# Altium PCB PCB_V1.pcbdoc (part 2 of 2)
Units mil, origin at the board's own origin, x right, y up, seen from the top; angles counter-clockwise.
Board outline 2047.24 x 3937.01 mil, 2 copper layers (Top Layer, Bottom Layer), stack 62.206 mil thick; 59 components, 45 nets, 231 pads, 209 vias.
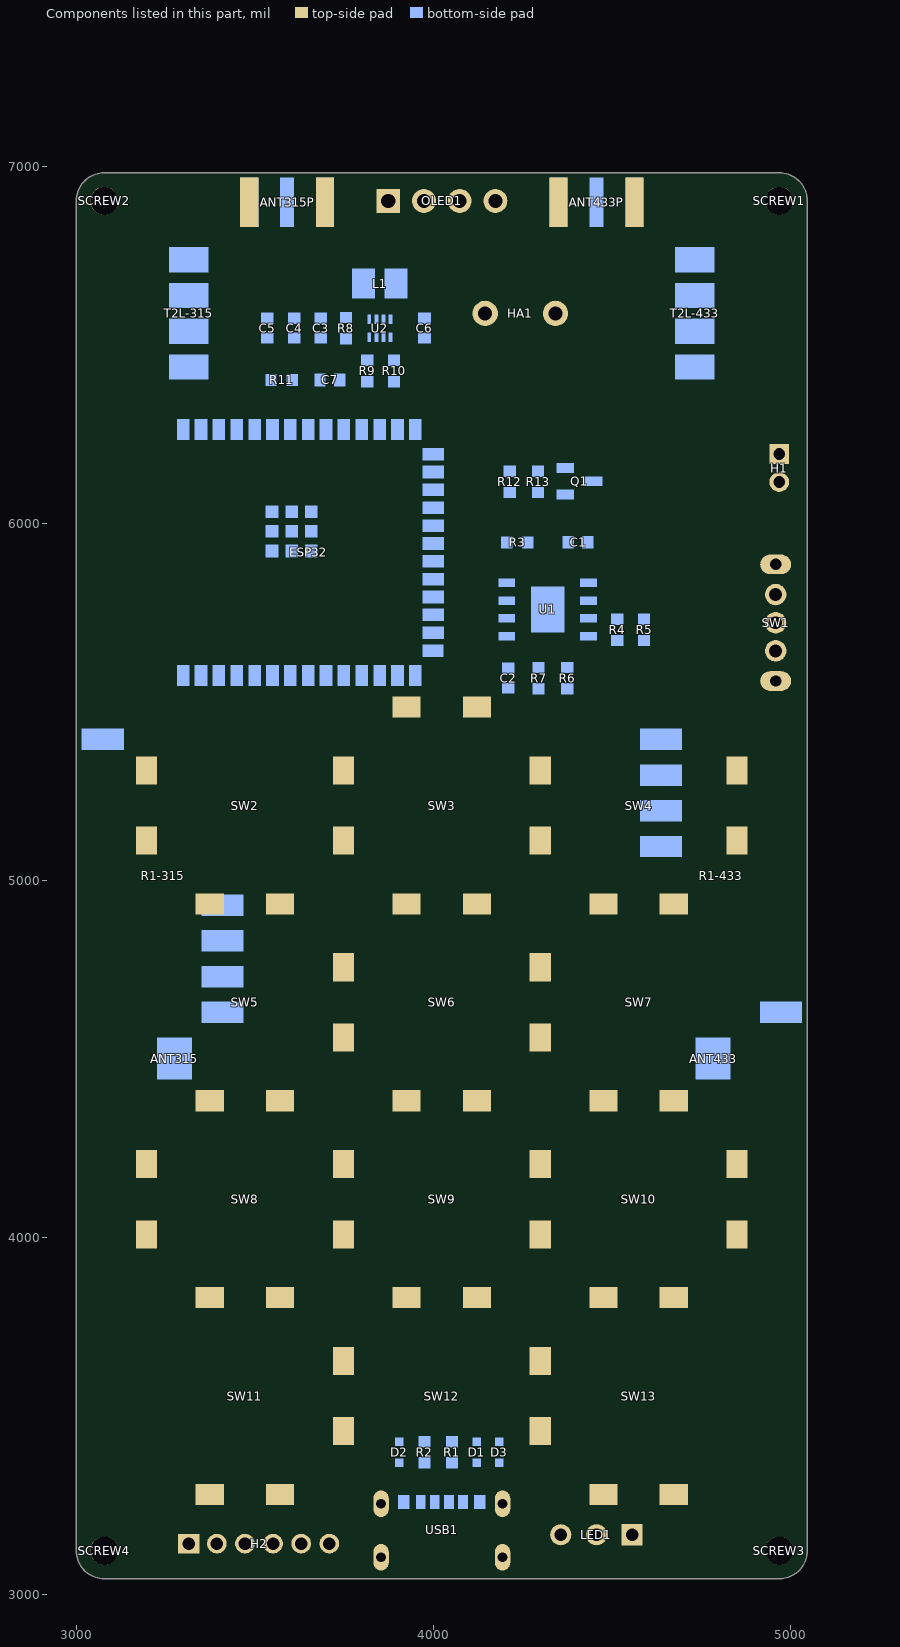
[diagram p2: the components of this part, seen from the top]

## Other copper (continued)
Bottom Layer:
  region net GND: 3530,6051.2 3675,6051.2 3675,5901.2 3530,5901.2
  region net $1N28916: 3907.72,6438.15 3871.33,6438.15 3871.46,6474.41 3854.1,6507.94 3854.1,6534.47 3885.01,6534.47 3885.16,6506.36 3907.72,6473.25
  region net $1N28920: 3833,6437.81 3797.28,6437.81 3797.28,6473.25 3760.6,6473.25 3735,6498.85 3735,6534.71 3826.2,6534.71 3826.2,6507 3833,6500.2
  region net EN: 3590.55,6416.94 3699.21,6416.94 3699.21,6383.48 3590.55,6383.48
  region net $1N28917: 3865.5,6557.67 3854.4,6557.67 3854.4,6585.15 3862.46,6628.72 3862.46,6716.2 3929.3,6716.2 3929.3,6626.2 3905.12,6626.2 3865.5,6587.16
  region net VCC: 3872.6,6557.82 3872.6,6585.62 3885.6,6585.6 3956.21,6590.6 3995,6590.6 3995,6557.82
  region net $1N28918: 3845.8,6557.89 3834.78,6557.89 3834.63,6584.73 3793.07,6626.56 3771.69,6626.52 3771.69,6716.14 3836.82,6716.14 3836.31,6715.63 3836.31,6628.63 3845.79,6584.73
  region net +3.3V: 3825.72,6584.7 3825.72,6556.75 3515.64,6556.75 3515.64,6591.31 3516.34,6592.01 3771.88,6592.01 3779.19,6584.7
  region net GND: 3994.86,6550.77 3994.79,6502.17 3994.68,6502.06 3955.99,6502.06 3955.56,6502.5 3955.56,6540.33 3954.93,6540.95 3851.52,6540.95 3845.82,6535.26 3845.82,6507.49 3834.35,6507.49 3834.35,6535.11 3828.54,6540.92 3710.47,6540.92 3703.19,6533.64 3703.19,6500.95 3516.92,6500.95 3516.28,6501.59 3516.28,6550.78
  region net GND: 3720.59,6419.62 3833.08,6419.62 3833.08,6380.39 3720.59,6380.39
  region net VBUS: 4095.18,3223.89 4070.18,3223.89 ccw(c3973.62,3223.89) 4068.9,3239.57 4096.46,3239.57 ccw(c4191.84,3223.89)
  region net VBUS: 4070.18,3293.88 4095.18,3293.88 ccw(c4183.03,3293.88) 4096.46,3278.94 4068.9,3278.94 ccw(c3982.32,3293.88)
  region net $1N28864: 4030.81,3316.44 4055.81,3316.44 ccw(c4605.98,3316.44) 4057.09,3278.94 4029.53,3278.94 ccw(c3480.63,3316.44)
  region net $1N28863: 3991.44,3316.44 4016.44,3316.44 ccw(c4566.61,3316.44) 4017.72,3278.94 3990.16,3278.94 ccw(c3441.26,3316.44)
  region net VBUS: 3977.07,3226.63 3952.07,3226.63 ccw(c3886.05,3226.63) 3950.79,3239.57 3978.35,3239.57 ccw(c4043.08,3226.63)
  region net TXD: 3599.85,3165.61 3606.93,3172.68 3608.05,3171.76 3609.35,3171.02 3610.81,3170.45 3612.39,3170.02 3615.84,3169.56 3619.47,3169.47 3623.08,3169.63 3626.46,3169.89 3629.38,3170.1 3631.65,3170.12 3602.42,3140.89 3602.44,3143.15 3602.65,3146.08 3602.91,3149.45 3603.06,3153.07 3602.98,3156.7 3602.51,3160.14 3602.09,3161.73 3601.52,3163.19 3600.78,3164.49
  region net EN: 3464.41,3177.75 3474.41,3182.3 3474.55,3180.85 3474.97,3179.4 3475.62,3177.95 3476.47,3176.51 3478.66,3173.71 3481.28,3171.04 3484.08,3168.58 3486.8,3166.38 3490.98,3163.01 3449.89,3158.46 3451.31,3160.11 3453.33,3162.06 3458.19,3166.69 3460.55,3169.3 3462.53,3172.04 3463.31,3173.44 3463.9,3174.87 3464.28,3176.31
  region net BOOT: 3423.77,3119.62 3416.69,3112.55 3415.57,3113.47 3414.27,3114.21 3412.81,3114.79 3411.23,3115.21 3407.78,3115.68 3404.15,3115.76 3400.54,3115.6 3397.16,3115.35 3394.24,3115.14 3391.97,3115.11 3421.21,3144.34 3421.18,3142.08 3420.97,3139.15 3420.71,3135.78 3420.56,3132.17 3420.64,3128.53 3421.11,3125.09 3421.53,3123.5 3422.1,3122.05 3422.84,3120.74
  region net CHG_P: 4176.53,5742.6 4182.67,5750.59 ccw(c4198.58,5771.81) 4198.58,5745.29 4181.83,5726.69 ccw(c4155.32,5726.69)
  region net CHG_P: 4181.27,5716.37 4176.53,5725.77 ccw(c4155.32,5741.68) 4181.83,5741.68 4197.18,5721.67 ccw(c4197.18,5695.15)
  region net B+: 4419.45,5890.29 4449.45,5890.29 ccw(c4571.18,5890.29) 4458.08,5845.29 4410.83,5845.29 ccw(c4297.69,5890.29)
  region net $1N7064: 4488.08,5793.48 4488.08,5773.48 ccw(c4488.08,5524.09) 4458.08,5771.67 4458.08,5795.29 ccw(c4488.08,6042.87)
  region net $1N6847: 4488.08,5739.68 4488.08,5719.68 ccw(c4458.08,5494.62) 4458.08,5721.67 4458.08,5745.29 ccw(c4488.08,5822.66)
  region net VBUS: 4446.95,5634.17 4421.95,5634.17 ccw(c4353.17,5634.17) 4410.83,5671.67 4458.08,5671.67 ccw(c4515.74,5634.17)
  region net VBUS: 4407.28,5673.48 4407.28,5693.48 ccw(c4407.28,5697.87) 4410.83,5695.29 4410.83,5671.67 ccw(c4407.28,5669.09)
  region net +3.3V: 3954.34,6859.33 3931.15,6878.56 3932.34,6879.87 3933.44,6881.29 3935.35,6884.4 3936.9,6887.75 3938.13,6891.18 3939.04,6894.54 3939.67,6897.68 3940.03,6900.44 3940.16,6902.69 3977.57,6869.22 3972.76,6868.36 3969.76,6867.58 3966.56,6866.54 3963.28,6865.21 3960.06,6863.58 3957.04,6861.63
  region net +3.3V: 4016.09,6878.56 3992.9,6859.33 3990.21,6861.63 3987.18,6863.58 3983.96,6865.21 3980.68,6866.54 3977.48,6867.58 3974.48,6868.36 3969.67,6869.22 4007.08,6902.69 4007.21,6900.44 4007.58,6897.68 4008.2,6894.54 4009.12,6891.18 4010.34,6887.75 4011.89,6884.4 4013.8,6881.29 4014.9,6879.87
  region net $1N7056: 4546.69,3227.14 4566.69,3227.14 ccw(c4604.19,3227.14) 4581.69,3197.14 4531.69,3197.14 ccw(c4509.19,3227.14)
  region net VBUS: 4437.11,3130.35 4419.43,3148.03 4421.43,3150.44 4423.07,3153.2 4424.39,3156.18 4425.41,3159.23 4426.17,3162.22 4426.71,3165.02 4427.22,3169.47 4458.54,3138.15 4454.09,3137.63 4451.3,3137.1 4448.31,3136.33 4445.26,3135.31 4442.28,3134 4439.52,3132.35
  region net $1N11631: 4378.05,3203.11 4392.19,3188.97 4391.16,3187.8 4390.26,3186.49 4388.82,3183.55 4387.79,3180.32 4387.1,3176.97 4386.66,3173.67 4386.41,3170.59 4386.16,3165.77 4354.84,3197.09 4359.67,3197.33 4362.75,3197.58 4366.05,3198.02 4369.4,3198.72 4372.63,3199.75 4375.57,3201.19 4376.88,3202.08
  region net 433_TX: 4832.4,6749.61 4832.4,6719.61 ccw(c4832.4,6653.12) 4787.4,6702.06 4787.4,6772.11 ccw(c4832.4,6805.86)
  region net +3.3V: 4635.52,6617.46 4635.52,6647.46 ccw(c4635.52,6697.25) 4677.17,6669.96 4677.17,6602.06 ccw(c4635.52,6553.42)
  region net GND: 4832.4,6551.2 4832.4,6521.2 ccw(c4832.4,6458.72) 4787.4,6502.06 4787.4,6572.93 ccw(c4832.4,6608.66)
  region net 433ANT: 4602.17,6412.49 4602.17,6462.49 ccw(c4602.17,6737.29) 4677.17,6472.93 4677.17,6402.06 ccw(c4602.17,6137.7)
  region net 433ANT: 4757.29,6327.06 4707.29,6327.06 ccw(c4598.84,6327.06) 4677.17,6402.06 4787.4,6402.06 ccw(c4865.73,6327.06)
  region net $1N15750: 4440,6176.36 4470,6176.36 ccw(c4818.76,6176.36) 4472.92,6131.36 4423.7,6131.36 ccw(c4369.73,6176.36)
  region net $1N6847: 4467.99,5719.68 4467.99,5739.68 ccw(c4467.99,5806.99) 4497.99,5746.73 4497.99,5714.98 ccw(c4467.99,5621.5)
  region net $1N11631: 4525,5625.66 4505,5625.66 ccw(c4437.28,5625.66) 4497.99,5655.66 4532.01,5655.66 ccw(c4592.72,5625.66)
  region net $1N7064: 4580,5756.2 4600,5756.2 ccw(c4609.9,5756.2) 4607.01,5746.73 4572.99,5746.73 ccw(c4570.1,5756.2)
  region net $1N7056: 4600,5625.66 4580,5625.66 ccw(c4512.28,5625.66) 4572.99,5655.66 4607.01,5655.66 ccw(c4667.72,5625.66)
  region net CHG_P: 4190.1,5923.89 4184.16,5932.09 ccw(c4162.95,5948) 4189.46,5948 4206.01,5929.19 ccw(c4206.01,5902.67)
  region net 433ANT: 4873.23,4525.88 4873.23,4475.88 ccw(c4873.23,4434.71) 4832.68,4441.83 4832.68,4559.94 ccw(c4873.23,4567.05)
  region net 315ANT: 3174.02,4475.88 3174.02,4525.88 ccw(c3174.02,4582.26) 3225.79,4559.94 3225.79,4441.83 ccw(c3174.02,4419.5)
  region net +3.3V: 4357.01,6539.29 4327.01,6539.29 4326.92,6541.16 4326.66,6543.03 4325.71,6546.77 4324.3,6550.41 4322.58,6553.87 4320.69,6557.05 4318.77,6559.88 4315.43,6564.09 4368.58,6564.09 4365.25,6559.88 4363.33,6557.05 4361.44,6553.87 4359.72,6550.41 4358.31,6546.77 4357.36,6543.03 4357.1,6541.16
  region net +3.3V: 4297.29,6611.03 4318.5,6632.24 4319.89,6630.99 4321.4,6629.84 4324.71,6627.87 4328.28,6626.29 4331.95,6625.07 4335.54,6624.15 4338.89,6623.51 4344.23,6622.89 4306.64,6585.31 4306.02,6590.65 4305.38,6594 4304.47,6597.59 4303.24,6601.25 4301.66,6604.82 4299.69,6608.14 4298.55,6609.65
  region net $1N15750: 4189.68,6562.73 4167.35,6542.63 4165.97,6543.89 4164.47,6545.04 4161.18,6547.02 4157.64,6548.62 4154.02,6549.88 4150.48,6550.83 4147.17,6551.52 4141.89,6552.25 4180.57,6588.7 4180.73,6586.29 4181.09,6583.31 4181.68,6579.91 4182.56,6576.28 4183.76,6572.58 4185.32,6568.97 4187.28,6565.63 4188.43,6564.12
  region net GND: 4953.5,6266.36 4983.5,6266.36 ccw(c5070.4,6266.36) 4996.06,6221.36 4940.94,6221.36 ccw(c4866.6,6266.36)
  region net B+: 4449.45,5883.48 4419.45,5883.48 ccw(c4034.87,5883.48) 4416.81,5928.48 4448.31,5928.48 ccw(c5332.55,5928.48)
  region net ADC: 4180.26,5553.29 4196.37,5565.46 ccw(c4227.72,5604.29) 4227.72,5554.39 4192.28,5522.89 ccw(c4147.85,5522.89)
  region net ADC: 4257.72,5548.64 4257.72,5528.64 ccw(c4257.72,5447.48) 4227.72,5522.89 4227.72,5554.39 ccw(c4257.72,5629.8)
  region net VCC: 4360,5635.71 4390,5635.71 ccw(c4534.16,5635.71) 4392.01,5611.73 4357.99,5611.73 ccw(c4215.84,5635.71)
  region net ADC: 4327.99,5528.64 4327.99,5548.64 ccw(c4327.99,5669.72) 4357.99,5552.41 4357.99,5520.66 ccw(c4327.99,5468.23)
  region net ADC: 4247.47,5528.64 4247.47,5548.64 ccw(c4247.47,5669.72) 4277.47,5552.41 4277.47,5520.66 ccw(c4247.47,5468.23)
  region net ADC: 4341.48,5548.64 4341.48,5528.64 ccw(c4341.48,5468.23) 4311.48,5520.66 4311.48,5552.41 ccw(c4341.48,5669.72)
  region net $1N15783: 4276.03,6101.03 4276.03,6071.03 ccw(c4276.03,4914.13) 4231.03,6070.15 4231.03,6101.9 ccw(c4276.03,7257.93)
  region net BUZZER: 4152.02,6130.35 4152.02,6160.35 ccw(c4152.02,7317.25) 4197.02,6161.22 4197.02,6129.47 ccw(c4152.02,4973.45)
  region net $1N15783: 4355.32,6095.18 4355.32,6065.18 ccw(c4310.32,5864.1) 4310.32,6070.15 4310.32,6101.9 ccw(c4355.32,6249.1)
  region net $1N15783: 4231.3,6071.03 4231.3,6101.03 ccw(c4231.3,7257.93) 4276.3,6101.9 4276.3,6070.15 ccw(c4231.3,4914.13)
  region net EN: 3599.17,6376.3 3580.25,6371.52 ccw(c3552.01,6399.75) 3588.78,6384.19 3612.49,6384.19 ccw(c3621.25,6354.22)
  region net +3.3V: 3507,6386.2 3507,6416.2 ccw(c3507,6542.86) 3529.46,6418.21 3529.46,6384.19 ccw(c3507,6259.53)
  region net 315ANT: 3099.02,5289.82 3049.02,5289.82 ccw(c2949.4,5289.82) 3014.96,5364.82 3133.07,5364.82 ccw(c3198.63,5289.82)
  region net 315ANT: 3049.02,5499.82 3099.02,5499.82 ccw(c3198.63,5499.82) 3133.07,5424.82 3014.96,5424.82 ccw(c2949.4,5499.82)
  region net 315_RX: 3379.69,4830.57 3439.69,4830.57 ccw(c3538.54,4830.57) 3468.74,4760.57 3350.63,4760.57 ccw(c3280.84,4830.57)
  region net 315_RX: 3439.69,4730.57 3379.69,4730.57 ccw(c3280.84,4730.57) 3350.63,4800.57 3468.74,4800.57 ccw(c3538.54,4730.57)
  region net 315_RX: 3491.37,4845.57 3491.37,4815.57 ccw(c3491.37,4791) 3468.74,4800.57 3468.74,4860.57 ccw(c3491.37,4870.14)
  region net +3.3V: 3394.41,5005.57 3424.41,5005.57 ccw(c3480.66,5005.57) 3446.91,4960.57 3371.91,4960.57 ccw(c3338.16,5005.57)
  region net 433ANT: 4972.99,4525.57 4873.23,4525.88 ccw(c4873.23,4574.45) 4914.17,4600.57 5032.28,4600.57 ccw(c6683.1,3234.58)
  region net 433ANT: 4948.23,4735.57 4998.23,4735.57 ccw(c5097.84,4735.57) 5032.28,4660.57 4914.17,4660.57 ccw(c4848.61,4735.57)
  region net 433_RX: 4667.56,5194.82 4607.56,5194.82 ccw(c4508.71,5194.82) 4578.5,5264.82 4696.61,5264.82 ccw(c4766.41,5194.82)
  region net 433_RX: 4607.56,5294.82 4667.56,5294.82 ccw(c4766.41,5294.82) 4696.61,5224.82 4578.5,5224.82 ccw(c4508.71,5294.82)
  region net 433_RX: 4717.52,5261.49 4736.84,5233.85 ccw(c17512.76,-2753.85) 4696.61,5169.15 4647.88,5224.82 ccw(c4647.88,5309.28)
  region net +3.3V: 4713.62,5109.82 4713.62,5079.82 ccw(c4713.62,5062.68) 4696.61,5064.82 4696.61,5124.82 ccw(c4713.62,5126.96)
  region net 315_TX: 3415.27,6429.5 3407.97,6396.58 ccw(c3385.28,6373.47) 3370.08,6402.07 3370.08,6471.05 ccw(c3560.59,6632.9)
  region net +3.3V: 3415.08,6552.5 3415.08,6522.5 ccw(c3415.08,6462.73) 3370.08,6502.07 3370.08,6572.93 ccw(c3415.08,6612.27)
  region net 315ANT: 3184.84,6712.5 3184.84,6762.5 ccw(c3184.84,7037.3) 3259.84,6772.93 3259.84,6702.07 ccw(c3184.84,6437.71)
  region net 315ANT: 3445.08,6762.5 3445.08,6712.5 ccw(c3445.08,6437.71) 3370.08,6702.07 3370.08,6772.93 ccw(c3445.08,7037.3)
  region net $1N28863: 3946.81,3378.86 3946.81,3358.86 ccw(c3946.81,3089.53) 3916.81,3357.19 3916.81,3380.81 ccw(c3946.81,3611.08)
  region net $1N28864: 4106.27,3381.36 4106.27,3356.36 ccw(c4106.27,3146.37) 4068.77,3352.99 4068.77,3384.74 ccw(c4106.27,3591.35)
  region net $1N28864: 4055.81,3315.49 4030.81,3315.49 ccw(c3854.73,3352.99) 4034.76,3352.99 4068.77,3352.99 ccw(c4116.52,3315.49)
  region net $1N28863: 3927.99,3358.86 3927.99,3378.86 ccw(c3927.99,3458.39) 3957.99,3384.74 3957.99,3352.99 ccw(c3927.99,3279.33)
  region net $1N28863: 4010.92,3350.62 3992.11,3334.07 ccw(c3942.07,3284.03) 3957.99,3352.99 3992.01,3384.74 ccw(c4060.96,3400.66)
  region net +3.3V: 3670,6634.51 3700,6634.51 ccw(c4074.08,6634.51) 3702.72,6589.51 3667.28,6589.51 ccw(c3295.92,6634.51)
  region net +3.3V: 3472.28,6559.2 3472.28,6589.2 ccw(c3472.28,9876.7) 3517.28,6589.51 3517.28,6558.01 ccw(c3472.28,5706.33)
  region net VCC: 4037.72,6588.76 4037.72,6558.76 ccw(c4037.72,5204.78) 3992.72,6558.01 3992.72,6589.51 ccw(c4037.72,7942.74)
  region net VCC: 3952.01,6410.94 3952.01,6380.94 ccw(c3952.01,2747.89) 3907.01,6380.66 3907.01,6412.41 ccw(c3952.01,7099.39)
  region net +3.3V: 3364.41,6188.17 3334.41,6188.17 ccw(c2959.97,6188.17) 3331.69,6233.17 3367.13,6233.17 ccw(c3738.14,6188.17)
  region net EN: 3387,6307.22 3397,6307.22 ccw(c3415.75,6307.22) 3404.5,6292.22 3381.69,6292.22 ccw(c3363.14,6307.22)
  region net EN: 3404.41,6218.17 3394.41,6218.17 ccw(c3375.66,6218.17) 3386.91,6233.17 3411.91,6233.17 ccw(c3423.16,6218.17)
  region net 315_TX: 3433.42,6335.93 3463.42,6335.93 ccw(c3722.86,6335.93) 3467.13,6292.22 3431.69,6292.22 ccw(c2879.13,6335.93)
  region net 315_RX: 3514.41,6202.61 3484.41,6202.61 ccw(c3311.17,6202.61) 3481.69,6233.17 3517.13,6233.17 ccw(c3687.66,6202.61)
  region net KEY_BACK: 3554.41,6228.17 3544.41,6228.17 ccw(c3536.91,6225.04) 3536.91,6233.17 3561.91,6233.17 ccw(c3561.91,6225.04)
  region net KEY_8: 3604.41,6218.17 3594.41,6218.17 ccw(c3575.66,6218.17) 3586.91,6233.17 3611.91,6233.17 ccw(c3623.16,6218.17)
  region net KEY_7: 3654.41,6228.17 3644.41,6228.17 ccw(c3636.91,6225.04) 3636.91,6233.17 3661.91,6233.17 ccw(c3661.91,6225.04)
  region net KEY_6: 3704.41,6228.17 3694.41,6228.17 ccw(c3686.91,6225.04) 3686.91,6233.17 3711.91,6233.17 ccw(c3711.91,6225.04)
  region net KEY_5: 3754.41,6218.17 3744.41,6218.17 ccw(c3725.66,6218.17) 3736.91,6233.17 3761.91,6233.17 ccw(c3773.16,6218.17)
  region net KEY_4: 3804.41,6218.17 3794.41,6218.17 ccw(c3775.66,6218.17) 3786.91,6233.17 3811.91,6233.17 ccw(c3823.16,6218.17)
  region net KEY_3: 3854.41,6218.17 3844.41,6218.17 ccw(c3825.66,6218.17) 3836.91,6233.17 3861.91,6233.17 ccw(c3873.16,6218.17)
  region net KEY_2: 3904.41,6218.17 3894.41,6218.17 ccw(c3875.66,6218.17) 3886.91,6233.17 3911.91,6233.17 ccw(c3923.16,6218.17)
  region net KEY_1: 3954.41,6218.17 3944.41,6218.17 ccw(c3925.66,6218.17) 3936.91,6233.17 3961.91,6233.17 ccw(c3973.16,6218.17)
  region net I2C_SDA: 3994.8,6225.92 4004.8,6225.92 ccw(c4023.55,6225.92) 4012.3,6210.92 3987.3,6210.92 ccw(c3976.05,6225.92)
  region net BUZZER: 4074.33,6107.2 4074.33,6077.2 ccw(c4074.33,5483.75) 4029.33,6075.49 4029.33,6110.92 ccw(c4074.33,6380.92)
  region net KEY_ENTER: 3960.27,6038.21 3960.27,6048.21 ccw(c3960.27,6058.62) 3970.27,6055.71 3970.27,6030.71 ccw(c3960.27,6027.79)
  region net KEY_MENU: 3968.06,5970.19 3964.97,5981.24 ccw(c3943.76,5997.15) 3970.27,5997.15 3983.97,5975.49 ccw(c3983.97,5948.97)
  region net 433_RX: 4074.33,5958.21 4074.33,5928.21 ccw(c4074.33,5554.12) 4029.33,5925.49 4029.33,5960.92 ccw(c4074.33,6332.29)
  region net 433_TX: 4074.33,5908.2 4074.33,5878.2 ccw(c4074.33,5503.88) 4029.33,5875.49 4029.33,5910.92 ccw(c4074.33,6282.04)
  region net ADC: 4034.33,5853.2 4034.33,5833.2 ccw(c4037.78,5825.49) 4029.33,5825.49 4029.33,5860.92 ccw(c4037.79,5860.92)
  region net KEY_9: 3960.27,5788.21 3960.27,5798.21 ccw(c3960.27,5808.62) 3970.27,5805.71 3970.27,5780.71 ccw(c3960.27,5777.79)
  region net BOOT: 3954.41,5529.19 3944.41,5529.19 ccw(c3925.66,5529.19) 3936.91,5544.19 3961.91,5544.19 ccw(c3973.16,5529.19)
  region net RXD: 3504.41,5529.19 3494.41,5529.19 ccw(c3475.66,5529.19) 3486.91,5544.19 3511.91,5544.19 ccw(c3523.16,5529.19)
  region net TXD: 3455,5529.19 3445,5529.19 ccw(c3426.25,5529.19) 3437.5,5544.19 3462.5,5544.19 ccw(c3473.75,5529.19)
  region net I2C_SCL: 3403.83,5611.14 3423.4,5616.57 ccw(c3445.48,5594.49) 3415.51,5603.24 3390.51,5603.24 ccw(c3381.75,5633.22)
  region net CHG_P: 3344.41,5613.24 3354.41,5613.24 ccw(c3364.83,5613.24) 3361.91,5603.24 3336.91,5603.24 ccw(c3333.99,5613.24)
  region net GND: 3314.41,5520.35 3284.41,5520.35 ccw(c3178.48,5520.35) 3281.69,5544.19 3317.13,5544.19 ccw(c3420.34,5520.35)
  region net RXD: 3494.41,5329.85 3504.41,5327.02 3504.69,5325.38 3505.43,5323.17 3506.47,5320.78 3507.66,5318.61 3489.88,5321.45 3491.54,5323.22 3492.99,5325.48 3494.02,5327.82 3494.31,5328.9
  region net KEY_BACK: 3545.87,6224.63 3552.94,6231.7 3553.89,6231.24 3555.64,6230.78 3557.84,6230.39 3560.16,6230.15 3547.42,6217.42 3547.18,6219.74 3546.8,6221.94 3546.34,6223.68
  region net KEY_ENTER: 4090.71,5563.54 4085.14,5554.97 4084.42,5555.55 4083.48,5556.1 4081.13,5557.03 4078.52,5557.64 4076.07,5557.79 4087.22,5571.93 4087.83,5569.53 4088.72,5567.06 4089.74,5564.94
  region net KEY_ENTER: 4264.31,5375.8 4271.38,5382.87 4272.91,5381.84 4275.15,5380.88 4277.7,5380.13 4280.16,5379.76 4267.42,5367.02 4267.05,5369.48 4266.31,5372.03 4265.35,5374.28
  region net KEY_1: 3785.88,5724.63 3792.95,5731.71 3793.9,5731.24 3795.64,5730.78 3797.84,5730.39 3800.16,5730.15 3787.43,5717.42 3787.19,5719.74 3786.8,5721.94 3786.34,5723.68
  region net KEY_1: 3681.39,5113.08 3674.32,5120.15 3675.35,5121.67 3676.31,5123.91 3677.05,5126.47 3677.43,5128.92 3690.16,5116.19 3687.71,5115.81 3685.15,5115.07 3682.91,5114.11
  region net KEY_1: 3647.44,5093.27 3654.51,5086.2 3653.47,5084.67 3652.51,5082.43 3651.77,5079.87 3651.4,5077.42 3638.66,5090.16 3641.11,5090.53 3643.67,5091.27 3645.91,5092.23
  region net KEY_2: 3787.44,6053.26 3794.51,6046.19 3793.47,6044.67 3792.51,6042.43 3791.77,6039.87 3791.4,6037.42 3778.66,6050.15 3781.11,6050.53 3783.67,6051.27 3785.91,6052.23
  region net KEY_2: 4097.14,4761.79 4097.14,4751.79 4095.33,4751.45 4093.07,4750.54 4090.74,4749.25 4088.74,4747.78 4088.74,4765.8 4090.74,4764.32 4093.07,4763.04 4095.33,4762.13
  region net KEY_2: 4144.45,4751.79 4144.45,4761.79 4146.25,4762.13 4148.52,4763.04 4150.85,4764.32 4152.85,4765.8 4152.85,4747.78 4150.85,4749.25 4148.52,4750.54 4146.25,4751.45
  region net KEY_3: 3844.41,6234.52 3854.41,6234.52 3854.76,6232.71 3855.66,6230.44 3856.95,6228.11 3858.42,6226.11 3840.41,6226.11 3841.88,6228.11 3843.16,6230.44 3844.07,6232.71
  region net KEY_4: 3782.93,5694.81 3790.01,5701.88 3791.53,5700.85 3793.77,5699.89 3796.33,5699.15 3798.78,5698.77 3786.05,5686.04 3785.67,5688.49 3784.93,5691.05 3783.97,5693.29
  region net KEY_4: 3753.03,5000.44 3743.03,5000.44 3742.69,5002.25 3741.78,5004.52 3740.49,5006.85 3739.02,5008.85 3757.04,5008.85 3755.57,5006.85 3754.28,5004.52 3753.37,5002.25
  region net KEY_4: 3731.68,4691.79 3731.68,4701.79 3733.49,4702.13 3735.76,4703.04 3738.09,4704.32 3740.09,4705.8 3740.09,4687.78 3738.09,4689.25 3735.76,4690.54 3733.49,4691.45
  region net KEY_4: 3743.03,4713.14 3753.03,4713.14 3753.37,4711.33 3754.28,4709.06 3755.57,4706.73 3757.04,4704.73 3739.02,4704.73 3740.49,4706.73 3741.78,4709.06 3742.69,4711.33
  region net KEY_4: 3466.05,4521.89 3473.13,4514.81 3472.09,4513.29 3471.13,4511.05 3470.39,4508.49 3470.01,4506.04 3457.28,4518.77 3459.73,4519.15 3462.29,4519.89 3464.53,4520.85
  region net KEY_5: 3727.44,6133.26 3734.51,6126.19 3733.47,6124.67 3732.51,6122.43 3731.77,6119.87 3731.4,6117.42 3718.66,6130.15 3721.11,6130.53 3723.67,6131.27 3725.91,6132.23
  region net KEY_6: 3695.87,6224.63 3702.94,6231.7 3703.89,6231.24 3705.64,6230.78 3707.84,6230.39 3710.16,6230.15 3697.42,6217.42 3697.18,6219.74 3696.8,6221.94 3696.34,6223.68
  region net KEY_7: 3597.43,6183.26 3604.5,6176.19 3603.47,6174.67 3602.51,6172.43 3601.77,6169.87 3601.39,6167.42 3588.66,6180.15 3591.11,6180.53 3593.67,6181.27 3595.91,6182.23
  region net KEY_8: 3564.31,6146.19 3571.38,6153.26 3572.91,6152.23 3575.15,6151.27 3577.71,6150.53 3580.16,6150.15 3567.42,6137.42 3567.05,6139.87 3566.31,6142.43 3565.35,6144.67
  region net KEY_9: 3871.51,5711.51 3880.08,5705.94 3879.5,5705.22 3878.95,5704.28 3878.02,5701.93 3877.41,5699.32 3877.26,5696.87 3863.11,5708.02 3865.52,5708.63 3867.99,5709.52 3870.11,5710.54
  region net I2C_SCL: 3474.98,5668.15 3467.91,5675.22 3468.95,5676.74 3469.91,5678.98 3470.65,5681.54 3471.02,5683.99 3483.76,5671.26 3481.31,5670.88 3478.75,5670.14 3476.51,5669.18
  region net B+: 4572.47,5822.87 4593.68,5844.09 4596.16,5841.95 4598.94,5840.12 4601.9,5838.58 4604.91,5837.32 4607.86,5836.34 4610.61,5835.62 4613.05,5835.15 4615.05,5834.92 4581.64,5801.51 4581.41,5803.51 4580.94,5805.95 4580.22,5808.7 4579.23,5811.64 4577.98,5814.65 4576.44,5817.61 4574.6,5820.39
  region net VCC: 4356.9,6238.04 4378.11,6259.26 4380.64,6257.07 4383.47,6255.18 4386.47,6253.59 4389.52,6252.28 4392.51,6251.25 4395.29,6250.5 4397.77,6250 4399.8,6249.76 4366.39,6216.35 4366.15,6218.39 4365.66,6220.86 4364.9,6223.65 4363.87,6226.63 4362.56,6229.69 4360.97,6232.69 4359.08,6235.52
  region net VCC: 4390,5613.13 4360,5612.07 4359.78,5615.6 4359.2,5619.07 4358.38,5622.43 4357.44,5625.62 4355.65,5631.31 4355.04,5633.69 4354.78,5635.71 4394.16,5636.77 4394.02,5634.76 4393.57,5632.38 4392.13,5626.7 4391.35,5623.5 4390.67,5620.14 4390.18,5616.66
  region net +3.3V: 4659.16,6647.46 4659.16,6617.46 4655.63,6617.25 4652.15,6616.72 4648.79,6615.97 4645.6,6615.11 4639.92,6613.49 4637.53,6612.96 4635.52,6612.76 4635.52,6652.16 4637.53,6651.95 4639.92,6651.42 4645.6,6649.81 4648.79,6648.94 4652.15,6648.19 4655.63,6647.66
  region net 433_TX: 4811.61,6719.61 4809.67,6749.61 4813.2,6749.84 4816.67,6750.44 4820.02,6751.31 4823.21,6752.31 4828.89,6754.22 4831.28,6754.89 4833.31,6755.2 4835.25,6715.85 4833.25,6715.94 4830.87,6716.34 4825.18,6717.64 4818.62,6718.99 4815.14,6719.43
  region net 433_TX: 4065.69,5878.2 4065.69,5908.2 4069.22,5908.41 4072.69,5908.94 4076.05,5909.69 4079.25,5910.55 4084.93,5912.17 4087.32,5912.7 4089.33,5912.9 4089.33,5873.5 4087.32,5873.71 4084.93,5874.24 4079.25,5875.85 4076.05,5876.72 4072.69,5877.47 4069.22,5878
  region net 433_RX: 4119.33,5866.84 4149.33,5866.84 4149.53,5863.31 4150.06,5859.84 4150.82,5856.48 4151.68,5853.29 4153.29,5847.6 4153.83,5845.22 4154.03,5843.2 4114.63,5843.2 4114.83,5845.22 4115.36,5847.6 4116.98,5853.29 4117.84,5856.48 4118.59,5859.84 4119.13,5863.31
  region net 433_RX: 4754.33,5319.57 4724.33,5319.57 4724.13,5323.1 4723.59,5326.57 4722.84,5329.93 4721.98,5333.12 4720.36,5338.81 4719.83,5341.19 4719.63,5343.21 4759.03,5343.21 4758.83,5341.19 4758.29,5338.81 4756.68,5333.12 4755.81,5329.93 4755.06,5326.57 4754.53,5323.1
  region net +3.3V: 3424.41,4984.53 3394.41,4984.53 3394.21,4988.06 3393.67,4991.54 3392.92,4994.9 3392.06,4998.09 3390.44,5003.77 3389.91,5006.16 3389.71,5008.17 3429.11,5008.17 3428.91,5006.16 3428.37,5003.77 3426.76,4998.09 3425.9,4994.9 3425.14,4991.54 3424.61,4988.06
  region net +3.3V: 3223.18,5200.03 3253.18,5200.03 3253.38,5196.5 3253.91,5193.03 3254.67,5189.67 3255.53,5186.47 3257.14,5180.79 3257.68,5178.4 3257.88,5176.39 3218.48,5176.39 3218.68,5178.4 3219.21,5180.79 3220.83,5186.47 3221.69,5189.67 3222.44,5193.03 3222.98,5196.5
  region net GND: 3360.42,4454.42 3390.42,4454.42 3390.62,4450.89 3391.15,4447.42 3391.9,4444.06 3392.77,4440.86 3394.38,4435.18 3394.91,4432.79 3395.12,4430.78 3355.72,4430.78 3355.92,4432.79 3356.45,4435.18 3358.07,4440.86 3358.93,4444.06 3359.68,4447.42 3360.21,4450.89
  region net GND: 3284.41,5528.75 3314.41,5535.44 3314.22,5534.81 3313.69,5534.18 3311.81,5532.91 3309.2,5531.68 3306.29,5530.51 3301.34,5528.47 3300.15,5527.67 3300.06,5527.33 3300.39,5527.04 3284,5520.35 3284.19,5521.49 3284.31,5523.48
  region net 315_RX: 3480.93,6187.31 3494.2,6155.33 3491.68,6153.03 3489.04,6150.84 3483.5,6146.79 3477.78,6143.2 3472.06,6140.09 3466.53,6137.48 3461.36,6135.4 3456.74,6133.86 3452.85,6132.88 3445.94,6171.66 3449.41,6172.24 3453.9,6173.12 3459.01,6174.35 3464.38,6175.98 3469.64,6178.04 3472.11,6179.25 3474.4,6180.58 3476.48,6182.05 3478.29,6183.66 3479.79,6185.41
  region net 315_RX: 3464,5367.56 3434,5367.56 3433.8,5371.09 3433.27,5374.56 3432.51,5377.92 3431.65,5381.12 3430.03,5386.8 3429.5,5389.19 3429.3,5391.2 3468.7,5391.2 3468.5,5389.19 3467.97,5386.8 3466.35,5381.12 3465.49,5377.92 3464.73,5374.56 3464.2,5371.09
  region net +3.3V: 3387.42,6522.5 3387.42,6552.5 3390.75,6552.74 3394.08,6553.41 3397.33,6554.4 3400.42,6555.64 3403.26,6557.02 3405.76,6558.46 3407.86,6559.86 3409.47,6561.13 3409.47,6513.88 3407.86,6515.15 3405.76,6516.55 3403.26,6517.98 3400.42,6519.36 3397.33,6520.6 3394.08,6521.59 3390.75,6522.26
  region net +3.3V: 3450.02,6578.43 3471.23,6557.22 3469.05,6554.69 3467.16,6551.86 3465.57,6548.86 3464.26,6545.81 3463.23,6542.82 3462.47,6540.04 3461.98,6537.56 3461.74,6535.53 3428.33,6568.94 3430.36,6569.18 3432.84,6569.67 3435.63,6570.43 3438.61,6571.46 3441.66,6572.77 3444.67,6574.36 3447.49,6576.25
  region net +3.3V: 3445.3,6494.62 3415.3,6494.62 3415.06,6497.95 3414.4,6501.28 3413.4,6504.53 3412.17,6507.62 3410.78,6510.45 3409.35,6512.96 3407.95,6515.06 3406.68,6516.67 3453.93,6516.67 3452.66,6515.06 3451.26,6512.96 3449.82,6510.45 3448.44,6507.62 3447.21,6504.53 3446.21,6501.28 3445.55,6497.95
  region net +3.3V: 3364.41,6132.49 3334.41,6132.49 3334.17,6135.82 3333.5,6139.16 3332.51,6142.41 3331.27,6145.49 3329.89,6148.33 3328.45,6150.84 3327.05,6152.93 3325.78,6154.54 3373.03,6154.54 3371.76,6152.93 3370.36,6150.84 3368.93,6148.33 3367.55,6145.49 3366.31,6142.41 3365.32,6139.16 3364.65,6135.82
  region net +3.3V: 3334.41,6218.26 3364.41,6218.26 3364.65,6214.93 3365.32,6211.59 3366.31,6208.34 3367.55,6205.26 3368.93,6202.42 3370.36,6199.91 3371.76,6197.82 3373.03,6196.21 3325.78,6196.21 3327.05,6197.82 3328.45,6199.91 3329.89,6202.42 3331.27,6205.26 3332.51,6208.34 3333.5,6211.59 3334.17,6214.93
  region net I2C_SDA: 4034.46,6363.09 4027.39,6370.16 4028.42,6371.69 4029.38,6373.93 4030.12,6376.48 4030.5,6378.93 4043.22,6366.2 4040.77,6365.83 4038.22,6365.09 4035.98,6364.13
  region net KEY_ENTER: 3930.91,5852.22 3937.98,5859.29 3939.51,5858.25 3941.75,5857.29 3944.3,5856.55 3946.75,5856.18 3934.02,5843.45 3933.65,5845.9 3932.91,5848.45 3931.95,5850.69
  region net KEY_MENU: 3943,5911.54 3953,5911.54 3953.34,5909.73 3954.25,5907.46 3955.53,5905.13 3957,5903.14 3939,5903.14 3940.47,5905.13 3941.75,5907.46 3942.66,5909.73
  region net CHG_P: 3926.44,5633.2 3924.94,5643.2 3925.83,5643.3 3926.86,5643.57 3929.17,5644.54 3931.46,5645.92 3933.34,5647.51 3934.84,5629.57 3932.75,5630.9 3930.38,5632.06 3928.15,5632.89
  region net CHG_P: 4105.05,5635.2 4105.05,5645.2 4106.86,5645.54 4109.12,5646.45 4111.45,5647.73 4113.45,5649.2 4113.45,5631.2 4111.45,5632.67 4109.12,5633.95 4106.86,5634.85
  region net CHG_P: 4068.34,5645.2 4068.34,5635.2 4066.53,5634.85 4064.26,5633.95 4061.93,5632.67 4059.94,5631.2 4059.94,5649.2 4061.93,5647.73 4064.26,5646.45 4066.53,5645.54
  region net CHG_P: 4179.15,5647.33 4185.47,5655.15 4187.06,5654.07 4189.36,5653.13 4191.94,5652.46 4194.4,5652.2 4182.44,5638.74 4181.95,5641.18 4181.14,5643.69 4180.15,5645.87
  region net EN: 3397,6339.86 3387,6339.86 3386.66,6341.67 3385.75,6343.94 3384.47,6346.26 3383,6348.26 3401,6348.26 3399.53,6346.26 3398.25,6343.94 3397.34,6341.67
  region net EN: 3408.09,6466.18 3401.02,6459.11 3399.49,6460.15 3397.25,6461.11 3394.7,6461.85 3392.25,6462.22 3404.98,6474.95 3405.35,6472.5 3406.09,6469.95 3407.05,6467.7
  region net VBUS: 3990,3188.7 cw(c3990,3017.84) 4081.14,3162.36 4098.82,3180.04 cw(c4121.91,3203.12) 4091.52,3215.06 4073.84,3232.73 cw(c3990,3407.85) 3990,3213.7
  region net VBUS: 4176.16,3350.04 cw(c4124.11,3402.09) 4129.82,3328.7 4160,3316.2 4215.18,3328.7 cw(c4215.18,3392.72) 4193.84,3332.36
  region net VCC: 4020.52,6447.14 ccw(c3914.46,6553.2) 4062.95,6531.99 4105.38,6510.78 4126.59,6468.35 ccw(c4147.8,6319.86) 4041.74,6425.92

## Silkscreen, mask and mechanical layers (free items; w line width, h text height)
Bottom Silkscreen Layer:
  drawing of 21 lines, arcs and shapes, not listed
  text "+  -" at 4945,6026.2 h100 r270
  text "BAT 503048 / 800mAh" at 4377.95,4461.51 h120
  text "RADIO FREQUENCY CONTROL V1" at 4565,3606.2 h72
